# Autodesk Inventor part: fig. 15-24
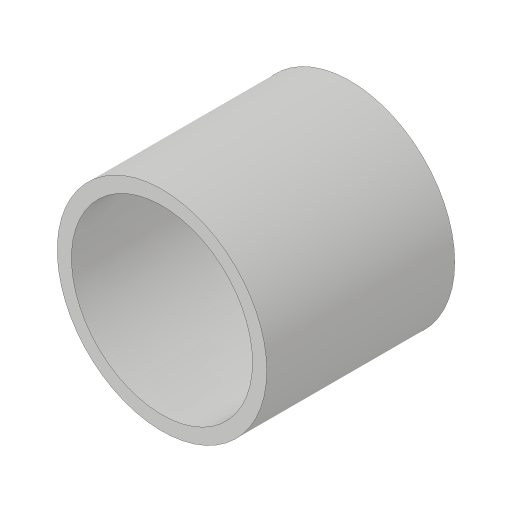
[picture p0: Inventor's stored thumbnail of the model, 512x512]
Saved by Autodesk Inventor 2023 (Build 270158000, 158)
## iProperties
Created: 2018-03
Part Number: fig. 15-24
Material: Generic
Document SubType Name: Modeling
Designer: CADCIM 00
Density: 1 g/cm^3
Appearance: Default
Author: CADCIM 00
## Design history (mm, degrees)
sketch "Sketch1"
  geometry: C1 r 14.209 at (0.32, 0); C2 r 12.286 at (0.32, 0); 1 further point
  constraints: 2 centre point, 1 coincident
  dimensions: "d0" = 25.5 dimension on point (0, 0) C1.centre C1 C2.centre C2
extrude "Extrusion1" new body sketch "Sketch1" distance "d0" = 25.5; taper "d1" = 0 deg
body "Solid1"
